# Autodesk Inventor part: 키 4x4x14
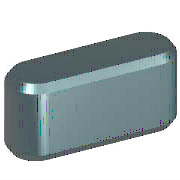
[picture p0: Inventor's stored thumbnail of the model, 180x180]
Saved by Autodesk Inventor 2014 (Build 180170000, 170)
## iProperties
IsCustomPart: 1
Created: 2012-02
Part Number: 키 4x4x14
Material: 강철, 연강
Description: 키 및 해당 키홈
Document SubType Name: Modeling
Standard: KS B 1311
Designer: mduedu
Standards Organization: KS
Language: ko-KR
Size Designation: 4 x 4 x 14
Categories: <MemberInstance><Categories><Category DisplayName="샤프트 부품" InternalName="7f7aeb1f-a693-4053-b835-cee3144e0d98" Mnemonic="SHFT"><Category DisplayName="키" Interna
Density: 1 g/cm^3
Appearance: 노란색
Author: mduedu
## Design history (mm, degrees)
workplane "Work Plane1"
workplane "Work Plane2"
sketch "스케치1"
  geometry: L1 (2, 2)-(12, 2); L2 (12, -2)-(2, -2); L3 (0, 9.4)-(0, -7.4) reference; L4 (-5, 0)-(30, 0) reference; L5 (14, 0)-(14, 7); A1 r 2 centre (2, 0) between (2, 2) and (2, -2); A2 r 2 centre (12, 0) between (12, -2) and (12, 2)
  constraints: 6 end point, 5 point on circle, 4 tangent, 3 point on line, 2 centre point, 1 horizontal, 1 parallel, 1 perpendicular
  dimensions: "d0" = 2 radius of A1 (= 0.5 x PB); "d13" = 2 radius of A2 (= 0.5 x PB); "d14" = 14 distance between parallel lines of L5 L3 (= NLG)
extrude "본체1" new body sketch "스케치1" taper "d3" = 0 deg; stored distance "d4" = 10
workplane "Work Plane3"
body "Solid1"
chamfer "모따기1" distance "d8" = 0.25 (= PHH); stored, may be unused: second distance "d9" = 0.25 (= PHH), angle "d15" = 45 deg
other parameters: "d1" = -2.5 (= -PNT), "d2" = 1.5 (= PH - PNT), "NLG" = 14 [user parameter; used in 3 equation terms], "PB" = 4 [user parameter; used in 2 equation terms], "PNT" = 2.5 [user parameter; used in 2 equation terms], "PH" = 4 [user parameter; used in 1 equation term], "PHH" = 0.25 [user parameter; used in 2 equation terms], "d10" = 0, "d16" = 0, "d17" = 0, "d18" = 0, "PLB2" = 14 (= NLG) [user parameter], "WDMAX" = 12 [user parameter], "PLB1" = 14 (= NLG) [user parameter], "RR" = 0.08 [user parameter], "PUEB" = 1.8 [user parameter]
